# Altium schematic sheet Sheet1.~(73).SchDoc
size A4; SheetNumber: 1; SheetTotal: 1
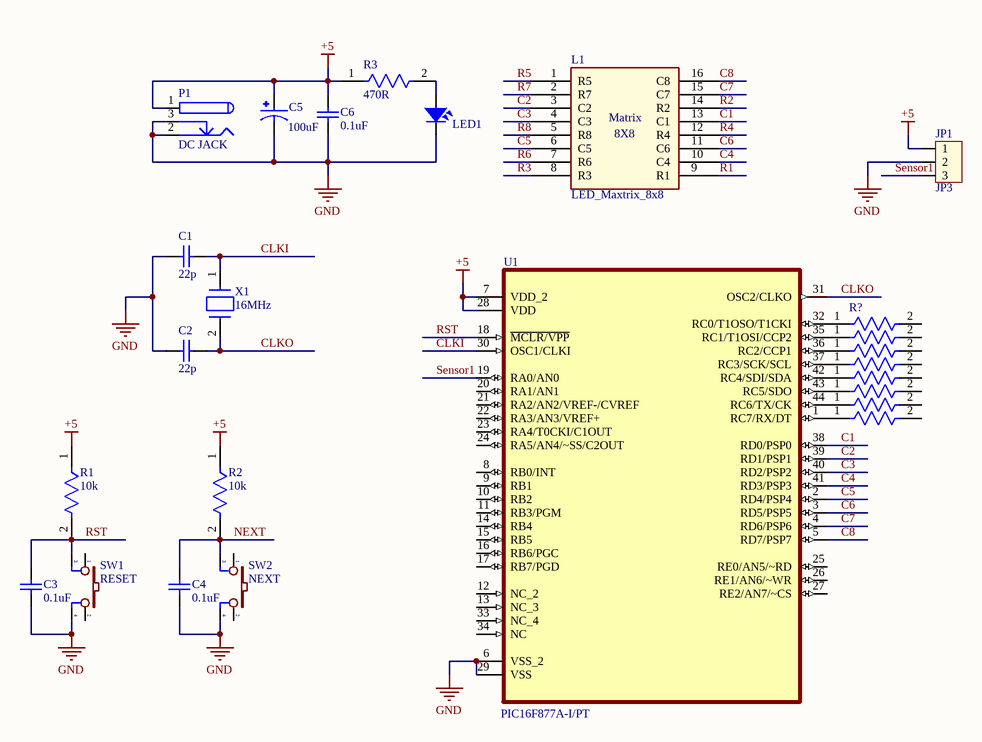
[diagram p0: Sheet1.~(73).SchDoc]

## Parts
(Parts that share a designator on the sheet are numbered #1, #2 ... from top to bottom, then left to right.)
C1  22p  [CAPC2013X94X50LL25T25]
C2  22p  [CAPC2013X94X50LL25T25]
C3  0.1uF  [CAPC2013X94X50LL25T25]
C4  0.1uF  [CAPC2013X94X50LL25T25]
C5  value 100uF  [FP-FKF-MFG]  (hidden comment: EEE-FK1H101GP)
C6  0.1uF  [CAPC2013X94X50LL25T25]
JP1  JP3  [CON3]
L1  LED_Maxtrix_8x8  [LED_Matrix_8x8]
LED1  LED SMD  [SM-LED-0805-Green]  (value not drawn)
P1  DC JACK  [DC5.5/2.1]
R1  10k  [FP-CR0805-MFG]
R2  10k  [FP-CR0805-MFG]
R3  470R  [FP-CR0805-IPC_A]
R?#1  330R  [FP-CR0805-IPC_A]  (value not drawn)
R?#2  330R  [FP-CR0805-IPC_A]  (value not drawn)
R?#3  330R  [FP-CR0805-IPC_A]  (value not drawn)
R?#4  330R  [FP-CR0805-IPC_A]  (value not drawn)
R?#5  330R  [FP-CR0805-IPC_A]  (value not drawn)
R?#6  330R  [FP-CR0805-IPC_A]  (value not drawn)
R?#7  330R  [FP-CR0805-IPC_A]  (value not drawn)
R?#8  330R  [FP-CR0805-IPC_A]  (value not drawn)
SW1  RESET  [SW4]
SW2  NEXT  [SW4]
U1  PIC16F877A-I/PT  [TQFP-44]
X1  16MHz  [FP-ABM7-MFG]

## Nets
+5: C5.1 C6.2 JP1.1 P1.1 R1.1 R2.1 R3.1 U1.7(VDD_2) U1.28(VDD)
GND: C1.1 C2.1 C3.1 C4.1 C5.2 C6.1 JP1.2 LED1.2 P1.2 P1.3 SW1.4 SW2.4 U1.6(VSS_2) U1.29(VSS)
C1: L1.13(C1) U1.38(RD0/PSP0)
C2: L1.3(C2) U1.39(RD1/PSP1)
C3: L1.4(C3) U1.40(RD2/PSP2)
C4: L1.10(C4) U1.41(RD3/PSP3)
C5: L1.6(C5) U1.2(RD4/PSP4)
C6: L1.11(C6) U1.3(RD5/PSP5)
C7: L1.15(C7) U1.4(RD6/PSP6)
C8: L1.16(C8) U1.5(RD7/PSP7)
CLKI: C1.2 U1.30(OSC1/CLKI) X1.1
CLKO: C2.2 U1.31(OSC2/CLKO) X1.2
NEXT: C4.2 R2.2 SW2.3
R1: L1.9(R1)
R2: L1.14(R2)
R3: L1.8(R3)
R4: L1.12(R4)
R5: L1.1(R5)
R6: L1.7(R6)
R7: L1.2(R7)
R8: L1.5(R8)
RST: C3.2 R1.2 SW1.3 U1.18(~{MCLR/VPP})
Sensor1: JP1.3 U1.19(RA0/AN0)
NetLED1_1: LED1.1 R3.2
NetR?#1_1: R?#1.1 U1.32(RC0/T1OSO/T1CKI)
NetR?#2_1: R?#2.1 U1.35(RC1/T1OSI/CCP2)
NetR?#3_1: R?#3.1 U1.36(RC2/CCP1)
NetR?#4_1: R?#4.1 U1.37(RC3/SCK/SCL)
NetR?#5_1: R?#5.1 U1.42(RC4/SDI/SDA)
NetR?#6_1: R?#6.1 U1.43(RC5/SDO)
NetR?#7_1: R?#7.1 U1.44(RC6/TX/CK)
NetR?#8_1: R?#8.1 U1.1(RC7/RX/DT)

Not connected (* = marked no-connect by the designer): R?#1 2; R?#2 2; R?#3 2; R?#4 2; R?#5 2; R?#6 2; R?#7 2; R?#8 2; SW1 1 2; SW2 1 2; U1 8(RB0/INT) 9(RB1) 10(RB2) 11(RB3/PGM) 12(NC_2) 13(NC_3) 14(RB4) 15(RB5) 16(RB6/PGC) 17(RB7/PGD) 20(RA1/AN1) 21(RA2/AN2/VREF-/CVREF) 22(RA3/AN3/VREF+) 23(RA4/T0CKI/C1OUT) 24(RA5/AN4/~SS/C2OUT) 25(RE0/AN5/~RD) 26(RE1/AN6/~WR) 27(RE2/AN7/~CS) 33(NC_4) 34(NC)

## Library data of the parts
C1-C4 C6 = LD051C104KAB2A: Cap Ceramic 0.1uF 100V X7R 10% SMD 0805 125°C Embossed T/R; Manufacturer: Kyocera AVX; Value: 100nF
C5 = EEE-FK1H101GP: Cap Aluminum 100uF 50V 20% (8 X 10.2mm) SMD 350mA 5000 hr 105°C T/R; Manufacturer: Panasonic; Life (Hours): 5000Hour; Leakage Current: 10mA; Impedance: 340mR
JP1 = Con3: Connector 3
LED1 = LED-SMD-0805
P1 = DC5.5/2.1: Low Voltage Power Supply Connector; Solder: WAVE
R1-R3 = CR0805-JW-331ELF: Res Thick Film 0805 330 Ohm 5% 1/8W ±200ppm/°C Molded SMD SMD Paper Tape on Plastic Reel; Manufacturer: Bourns; Value: 330R; Power Rating: 125mW; Voltage Rating: 150V
R?#1-R?#8 = CR0805-JW-331ELF: Res Thick Film 0805 330 Ohm 5% 1/8W ±200ppm/°C Molded SMD SMD Paper Tape on Plastic Reel; Manufacturer: Bourns; Power Rating: 125mW; Voltage Rating: 150V
SW1 SW2 = SW4-1: Switch button 4 pin; Value: SW chip 4 pin
U1 = PIC16F877A-I/PT: PIC16F877A Microcontroller IC 8-Bit 20MHz 14KB _8K x 14_ FLASH 44-TQFP _10x10_; MF: Microchip
X1 = ABM7-16.000MHZ-4-T: Crystal 16MHz ±30ppm (Tol) ±50ppm (Stability) 18pF FUND 50Ohm 2-Pin Mini-CSMD T/R; Manufacturer: Abracon; ESR (Equivalent Series Resistance): 50R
